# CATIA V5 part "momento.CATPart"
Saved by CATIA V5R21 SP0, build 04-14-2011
Part number: Part1
Material "Steel": density 7860 kg/m3, Young's modulus 2e+11 Pa, Poisson ratio 0.266, thermal expansion 1.17e-05 1/K
Bounding box of the stored display mesh (mm): x -25 to 25, y -24.818 to 80, z 0 to 80
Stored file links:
  C:\Users\David\Desktop\TFG\catia\momento.CATPart
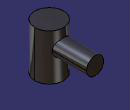
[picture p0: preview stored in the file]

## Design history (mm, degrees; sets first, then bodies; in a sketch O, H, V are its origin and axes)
Body1 (main body), material "Steel"
  Sketch1 on xy-plane, origin (0, 0, 0), H (1, 0, 0), V (0, 1, 0)
    circle A1 centre (0, 0) radius 25
    radius A1 = 25
  Pad1: profile Sketch1, direction (0, 0, 1), length 80
  Sketch2 on zx-plane, origin (0, 0, 0), H (-1, 0, 0), V (0, 0, 1)
    circle A1 centre (0, 50) radius 15
    point P1 (0, 50)
    radius A1 = 15
    distance H P1 = 50
    coincidence: P1 V
  Pad2: profile Sketch2, direction (0, 1, 0), length 80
